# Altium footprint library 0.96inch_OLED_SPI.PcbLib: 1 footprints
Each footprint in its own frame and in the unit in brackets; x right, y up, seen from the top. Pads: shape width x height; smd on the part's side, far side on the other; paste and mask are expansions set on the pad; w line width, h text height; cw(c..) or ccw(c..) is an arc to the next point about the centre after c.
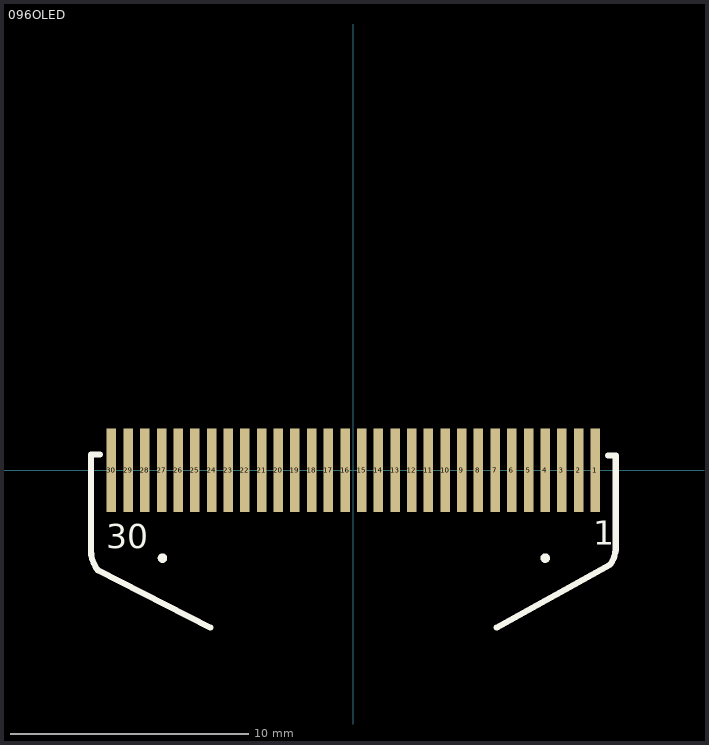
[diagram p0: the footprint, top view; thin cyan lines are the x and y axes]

## 096OLED [mm]
pads (30):
  rect 0.4x3.5 smd: 1(10.15,0) 2(9.45,0) 3(8.75,0) 4(8.05,0) 5(7.35,0) 6(6.65,0) 7(5.95,0) 8(5.25,0) 9(4.55,0) 10(3.85,0) 11(3.15,0) 12(2.45,0) 13(1.75,0) 14(1.05,0) 15(0.35,0) 16(-0.35,0) 17(-1.05,0) 18(-1.75,0) 19(-2.45,0) 20(-3.15,0) 21(-3.85,0) 22(-4.55,0) 23(-5.25,0) 24(-5.95,0) 25(-6.65,0) 26(-7.35,0) 27(-8.05,0) 28(-8.75,0) 29(-9.45,0) 30(-10.15,0)
Top Overlay:
  circle w0.2: c8.05,-3.68 r0.1
  circle w0.2: c-8.01,-3.68 r0.1
  lines w0.254: -11.012,-3.365 ccw(c-9.715,-3.365) -10.708,-4.199 -6,-6.6 ; -11.01,-3.365 -11.01,0.673 -10.639,0.673 ; -11.01,-2.645 -11.01,-1.6 ; 6,-6.6 10.765,-3.955 ccw(c9.999,-3.312) 10.999,-3.312 ; 10.678,0.635 11.01,0.635 11.01,-3.365 ; 11.008,-2.362 11.008,-2.311 ; 11.01,-2.564 11.01,-2.057
  text "1" at 10.058,-3.124 h1.02
  text "30" at -10.363,-3.277 h1.02
Bottom Overlay:
  lines w0.254: -13.325,14.69 -13.325,-4.57 13.375,-4.57 ; -13.325,14.691 13.375,14.691 ; 13.378,-4.57 13.378,14.69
